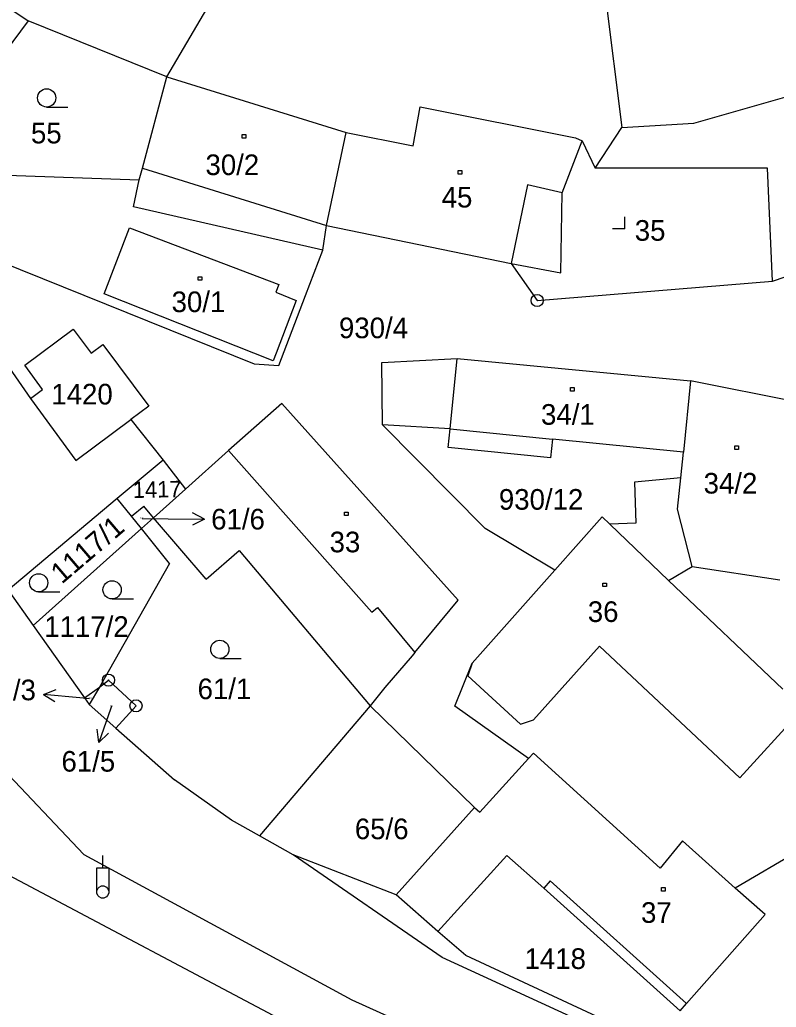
# Model space of a CAD drawing. Extents: x -796130 to -793145, y -1109506 to -1106267.
# Drawn here: x -794442.6 to -794380.3, y -1107911.5 to -1107830.1 of the extents above; entities that cross this region are included whole.
import ezdxf

# ---------------------------------------------------------------- set-up
doc = ezdxf.new("R2010")
doc.units = 0
for name, color, linetype in [('Komunikace', 7, 'Continuous'), ('Vrstva 1', 7, 'Continuous'), ('Vrstva 14', 7, 'Continuous'), ('Vrstva 15', 7, 'Continuous'), ('Vrstva 16', 7, 'Continuous'), ('Vrstva 2', 7, 'Continuous'), ('Vrstva 23', 7, 'Continuous'), ('Vrstva 25', 7, 'Continuous'), ('Vrstva 26', 7, 'Continuous'), ('Vrstva 28', 7, 'Continuous')]:
    doc.layers.add(name, color=color, linetype=linetype)

msp = doc.modelspace()

# ---------------------------------------------------------------- linework, layer by layer
at = {"layer": 'Komunikace'}
for p, q in [((-794432.56, -1107871.2), (-794430.41, -1107871.22)), ((-794436.9, -1107886.04), (-794437.7, -1107885.97)), ((-794435.07, -1107886.66), (-794435.13, -1107886.82))]:
    msp.add_line(p, q, dxfattribs=at)
at = {"layer": 'Vrstva 1'}
for p, q in [((-794395.39, -1107820.21), (-794393.06, -1107838.97)), ((-794430.51, -1107834.81), (-794422.52, -1107821.15)), ((-794453.1, -1107822.64), (-794441.95, -1107830.18)), ((-794441.95, -1107830.18), (-794444.77, -1107833.97)), ((-794430.51, -1107834.81), (-794441.95, -1107830.18)), ((-794432.52, -1107842.33), (-794430.51, -1107834.81)), ((-794430.51, -1107834.81), (-794415.75, -1107839.4)), ((-794387.13, -1107838.61), (-794372.24, -1107834.39)), ((-794410.24, -1107840.5), (-794409.66, -1107837.28)), ((-794409.66, -1107837.28), (-794396.87, -1107839.84)), ((-794393.06, -1107838.97), (-794387.13, -1107838.61)), ((-794417.38, -1107847.06), (-794415.75, -1107839.4)), ((-794415.75, -1107839.4), (-794410.24, -1107840.5)), ((-794395.24, -1107842.33), (-794393.06, -1107838.97)), ((-794397.98, -1107844.36), (-794396.32, -1107840.08)), ((-794396.87, -1107839.84), (-794396.32, -1107840.08)), ((-794396.32, -1107840.08), (-794395.24, -1107842.33)), ((-794445.24, -1107842.84), (-794432.79, -1107843.3)), ((-794432.79, -1107843.3), (-794432.52, -1107842.33)), ((-794381.05, -1107842.34), (-794395.24, -1107842.33)), ((-794380.64, -1107851.64), (-794381.05, -1107842.34)), ((-794433.26, -1107845.52), (-794432.79, -1107843.3)), ((-794398.07, -1107850.95), (-794397.98, -1107844.36)), ((-794417.69, -1107849.09), (-794433.26, -1107845.52)), ((-794417.69, -1107849.09), (-794417.38, -1107847.06)), ((-794417.38, -1107847.06), (-794402.16, -1107850.17)), ((-794451.41, -1107847.35), (-794441.76, -1107861.32)), ((-794380.64, -1107851.64), (-794371.7, -1107848.58)), ((-794419.11, -1107852.83), (-794417.69, -1107849.09)), ((-794444.34, -1107850), (-794423.33, -1107858.45)), ((-794402.16, -1107850.17), (-794398.07, -1107850.95)), ((-794402.16, -1107850.17), (-794400.02, -1107853.23)), ((-794400.02, -1107853.23), (-794380.64, -1107851.64)), ((-794421.31, -1107858.58), (-794419.11, -1107852.83)), ((-794442.22, -1107858.55), (-794438.24, -1107855.59)), ((-794438.24, -1107855.59), (-794436.75, -1107857.57)), ((-794436.75, -1107857.57), (-794435.79, -1107856.85)), ((-794435.79, -1107856.85), (-794432.01, -1107861.93)), ((-794423.33, -1107858.45), (-794421.31, -1107858.58)), ((-794412.83, -1107858.33), (-794406.62, -1107858)), ((-794412.75, -1107863.49), (-794412.83, -1107858.33)), ((-794406.62, -1107858), (-794387.41, -1107859.84)), ((-794440.76, -1107860.57), (-794442.22, -1107858.55)), ((-794387.41, -1107859.84), (-794387.99, -1107865.72)), ((-794378.6, -1107861.62), (-794387.41, -1107859.84)), ((-794441.76, -1107861.32), (-794440.76, -1107860.57)), ((-794441.76, -1107861.32), (-794438.01, -1107866.41)), ((-794432.01, -1107861.93), (-794433.5, -1107863.04)), ((-794421.05, -1107861.72), (-794425.45, -1107865.58)), ((-794406.54, -1107877.92), (-794421.05, -1107861.72)), ((-794438.01, -1107866.41), (-794433.5, -1107863.04)), ((-794433.5, -1107863.04), (-794430.83, -1107866.38)), ((-794404.3, -1107872.03), (-794412.75, -1107863.49)), ((-794407.2, -1107863.81), (-794412.75, -1107863.49)), ((-794407.35, -1107865.35), (-794407.2, -1107863.81)), ((-794398.77, -1107864.65), (-794398.92, -1107866.19)), ((-794387.99, -1107865.72), (-794398.77, -1107864.65)), ((-794428.98, -1107868.78), (-794425.45, -1107865.58)), ((-794398.92, -1107866.19), (-794407.35, -1107865.35)), ((-794388.21, -1107867.85), (-794387.99, -1107865.72)), ((-794430.83, -1107866.38), (-794434.61, -1107869.56)), ((-794430.83, -1107866.38), (-794428.98, -1107868.78)), ((-794388.21, -1107867.85), (-794392.01, -1107868.19)), ((-794392.01, -1107868.19), (-794391.91, -1107871.59)), ((-794428.98, -1107868.78), (-794431.61, -1107871.13)), ((-794434.61, -1107869.56), (-794443.59, -1107877.11)), ((-794433.44, -1107871), (-794434.61, -1107869.56)), ((-794433.44, -1107871), (-794432.43, -1107870.17)), ((-794431.61, -1107871.13), (-794432.43, -1107870.17)), ((-794432.61, -1107872.03), (-794433.44, -1107871)), ((-794431.61, -1107871.13), (-794432.61, -1107872.03)), ((-794427.29, -1107876.2), (-794431.61, -1107871.13)), ((-794394.67, -1107871.07), (-794398.56, -1107875.44)), ((-794394.04, -1107871.67), (-794394.67, -1107871.07)), ((-794432.61, -1107872.03), (-794441.54, -1107880)), ((-794430.29, -1107874.91), (-794432.61, -1107872.03)), ((-794398.56, -1107875.44), (-794404.3, -1107872.03)), ((-794391.91, -1107871.59), (-794394.04, -1107871.67)), ((-794389.2, -1107876.29), (-794394.04, -1107871.67)), ((-794427.29, -1107876.2), (-794424.58, -1107873.83)), ((-794424.58, -1107873.83), (-794413.78, -1107886.62)), ((-794430.29, -1107874.91), (-794436.08, -1107885.08)), ((-794405.39, -1107883.11), (-794398.56, -1107875.44)), ((-794389.2, -1107876.29), (-794387.27, -1107875.15)), ((-794387.27, -1107875.15), (-794380.04, -1107876.26)), ((-794379.8, -1107885.26), (-794389.2, -1107876.29)), ((-794443.59, -1107877.11), (-794441.54, -1107880)), ((-794410.09, -1107882.23), (-794406.54, -1107877.92)), ((-794441.54, -1107880), (-794437.3, -1107885.98)), ((-794410.33, -1107882.52), (-794412.56, -1107885.12)), ((-794410.09, -1107882.23), (-794410.33, -1107882.52)), ((-794406.8, -1107886.65), (-794405.39, -1107883.11)), ((-794437.3, -1107885.98), (-794436.08, -1107885.08)), ((-794436.08, -1107885.08), (-794436.91, -1107886.53)), ((-794436.08, -1107885.08), (-794435.32, -1107884.51)), ((-794435.32, -1107884.51), (-794433.06, -1107886.63)), ((-794412.56, -1107885.12), (-794413.78, -1107886.62)), ((-794437.3, -1107885.98), (-794436.91, -1107886.53)), ((-794436.91, -1107886.53), (-794434.71, -1107888.47)), ((-794433.06, -1107886.63), (-794434.71, -1107888.47)), ((-794413.78, -1107886.62), (-794422.9, -1107897.35)), ((-794413.78, -1107886.62), (-794405.18, -1107895.01)), ((-794400.75, -1107890.98), (-794406.8, -1107886.65)), ((-794434.71, -1107888.47), (-794429.88, -1107892.72)), ((-794404.76, -1107895.4), (-794400.75, -1107890.98)), ((-794400.75, -1107890.98), (-794400.33, -1107890.52)), ((-794389.89, -1107900), (-794400.33, -1107890.52)), ((-794425.2, -1107896.05), (-794429.88, -1107892.72)), ((-794405.18, -1107895.01), (-794411.63, -1107902.2)), ((-794405.18, -1107895.01), (-794404.76, -1107895.4)), ((-794422.9, -1107897.35), (-794425.2, -1107896.05)), ((-794420.12, -1107898.91), (-794422.9, -1107897.35)), ((-794447.88, -1107898.28), (-794403.89, -1107921.59)), ((-794388.06, -1107897.76), (-794389.89, -1107900)), ((-794383.71, -1107901.64), (-794388.06, -1107897.76)), ((-794377.92, -1107898.25), (-794383.71, -1107901.64)), ((-794411.63, -1107902.2), (-794420.12, -1107898.91)), ((-794408.22, -1107905.21), (-794402.53, -1107898.96)), ((-794399.48, -1107901.64), (-794402.53, -1107898.96)), ((-794408.22, -1107905.21), (-794411.63, -1107902.2)), ((-794388.26, -1107911.75), (-794399.48, -1107901.64)), ((-794381.26, -1107903.83), (-794383.71, -1107901.64)), ((-794387.73, -1107911.15), (-794381.26, -1107903.83)), ((-794405.89, -1107907.21), (-794408.22, -1107905.21)), ((-794391.58, -1107913.85), (-794405.89, -1107907.21)), ((-794388.26, -1107911.75), (-794387.73, -1107911.15))]:
    msp.add_line(p, q, dxfattribs=at)
at = {"layer": 'Vrstva 16'}
for p, q in [((-794430.41, -1107871.22), (-794427.41, -1107871.245)), ((-794427.41, -1107871.245), (-794428.414, -1107871.736)), ((-794427.41, -1107871.245), (-794428.405, -1107870.736)), ((-794440.687, -1107885.693), (-794439.645, -1107885.288)), ((-794437.7, -1107885.97), (-794440.687, -1107885.693)), ((-794440.687, -1107885.693), (-794439.737, -1107886.283)), ((-794435.13, -1107886.82), (-794436.123, -1107889.65)), ((-794436.123, -1107889.65), (-794436.264, -1107888.541)), ((-794436.123, -1107889.65), (-794435.32, -1107888.872))]:
    msp.add_line(p, q, dxfattribs=at)
at = {"layer": 'Vrstva 2'}
for p, q in [((-794432.52, -1107842.33), (-794417.38, -1107847.06)), ((-794400.81, -1107843.7), (-794402.16, -1107850.17)), ((-794397.98, -1107844.36), (-794400.81, -1107843.7)), ((-794435.68, -1107852.67), (-794433.6, -1107847.25)), ((-794433.6, -1107847.25), (-794421.31, -1107851.92)), ((-794421.31, -1107851.92), (-794421.56, -1107852.55)), ((-794421.78, -1107858.2), (-794435.68, -1107852.67)), ((-794421.56, -1107852.55), (-794419.86, -1107853.22)), ((-794419.86, -1107853.22), (-794421.53, -1107857.56)), ((-794421.53, -1107857.56), (-794421.78, -1107858.2)), ((-794407.2, -1107863.81), (-794406.62, -1107858)), ((-794407.2, -1107863.81), (-794398.77, -1107864.65)), ((-794425.45, -1107865.58), (-794413.64, -1107878.92)), ((-794388.47, -1107870.42), (-794388.21, -1107867.85)), ((-794387.27, -1107875.15), (-794388.47, -1107870.42)), ((-794413.64, -1107878.92), (-794413.18, -1107878.54)), ((-794413.18, -1107878.54), (-794410.09, -1107882.23)), ((-794400.34, -1107887.78), (-794394.89, -1107881.71)), ((-794394.89, -1107881.71), (-794383.35, -1107892.55)), ((-794405.39, -1107883.11), (-794405.73, -1107884.16)), ((-794405.73, -1107884.16), (-794401.39, -1107888.14)), ((-794383.35, -1107892.55), (-794378.14, -1107886.86)), ((-794448.11, -1107887.49), (-794437.37, -1107898.89)), ((-794401.39, -1107888.14), (-794400.34, -1107887.78)), ((-794437.37, -1107898.89), (-794415.3, -1107910.85)), ((-794407.86, -1107907.36), (-794420.12, -1107898.91)), ((-794398.95, -1107901.05), (-794399.48, -1107901.64)), ((-794387.73, -1107911.15), (-794398.95, -1107901.05)), ((-794299.63, -1107957.06), (-794407.86, -1107907.36)), ((-794415.3, -1107910.85), (-794361.74, -1107934.98))]:
    msp.add_line(p, q, dxfattribs=at)
at = {"layer": 'Vrstva 23'}
for p, q in [((-794440.42, -1107837.29), (-794438.67, -1107837.29)), ((-794392.82, -1107847.33), (-794392.82, -1107846.33)), ((-794392.82, -1107847.33), (-794393.82, -1107847.33)), ((-794441.08, -1107877.24), (-794439.33, -1107877.24)), ((-794435.03, -1107877.82), (-794433.28, -1107877.82)), ((-794426.16, -1107882.72), (-794424.41, -1107882.72))]:
    msp.add_line(p, q, dxfattribs=at)
for centre in [(-794440.42, -1107836.54), (-794441.08, -1107876.49), (-794435.03, -1107877.07), (-794426.16, -1107881.97)]:
    msp.add_circle(centre, 0.75, dxfattribs=at)
at = {"layer": 'Vrstva 25'}
for p, q in [((-794424.33, -1107839.55), (-794424.03, -1107839.55)), ((-794424.33, -1107839.85), (-794424.33, -1107839.55)), ((-794424.03, -1107839.55), (-794424.03, -1107839.85)), ((-794424.03, -1107839.85), (-794424.33, -1107839.85)), ((-794406.52, -1107842.51), (-794406.22, -1107842.51)), ((-794406.52, -1107842.81), (-794406.52, -1107842.51)), ((-794406.22, -1107842.81), (-794406.52, -1107842.81)), ((-794406.22, -1107842.51), (-794406.22, -1107842.81)), ((-794427.94, -1107851.27), (-794427.64, -1107851.27)), ((-794427.94, -1107851.57), (-794427.94, -1107851.27)), ((-794427.64, -1107851.57), (-794427.94, -1107851.57)), ((-794427.64, -1107851.27), (-794427.64, -1107851.57)), ((-794397.29, -1107860.41), (-794396.99, -1107860.41)), ((-794397.29, -1107860.71), (-794397.29, -1107860.41)), ((-794396.99, -1107860.71), (-794397.29, -1107860.71)), ((-794396.99, -1107860.41), (-794396.99, -1107860.71)), ((-794383.76, -1107865.2), (-794383.46, -1107865.2)), ((-794383.76, -1107865.5), (-794383.76, -1107865.2)), ((-794383.46, -1107865.5), (-794383.76, -1107865.5)), ((-794383.46, -1107865.2), (-794383.46, -1107865.5)), ((-794415.88, -1107870.66), (-794415.58, -1107870.66)), ((-794415.88, -1107870.96), (-794415.88, -1107870.66)), ((-794415.58, -1107870.96), (-794415.88, -1107870.96)), ((-794415.58, -1107870.66), (-794415.58, -1107870.96)), ((-794394.63, -1107876.51), (-794394.33, -1107876.51)), ((-794394.63, -1107876.81), (-794394.63, -1107876.51)), ((-794394.33, -1107876.81), (-794394.63, -1107876.81)), ((-794394.33, -1107876.51), (-794394.33, -1107876.81)), ((-794389.8, -1107901.59), (-794389.5, -1107901.59)), ((-794389.8, -1107901.89), (-794389.8, -1107901.59)), ((-794389.5, -1107901.89), (-794389.8, -1107901.89)), ((-794389.5, -1107901.59), (-794389.5, -1107901.89))]:
    msp.add_line(p, q, dxfattribs=at)
at = {"layer": 'Vrstva 26'}
for p, q in [((-794435.8, -1107899.97), (-794435.8, -1107898.97)), ((-794436.3, -1107901.97), (-794436.3, -1107899.97)), ((-794436.3, -1107899.97), (-794435.3, -1107899.97)), ((-794435.3, -1107899.97), (-794435.3, -1107901.97)), ((-794436.2, -1107901.67), (-794436.1, -1107901.57)), ((-794436.1, -1107901.57), (-794435.9, -1107901.47)), ((-794435.9, -1107901.47), (-794435.7, -1107901.47)), ((-794435.7, -1107901.47), (-794435.5, -1107901.57)), ((-794435.5, -1107901.57), (-794435.4, -1107901.67)), ((-794436.3, -1107901.87), (-794436.2, -1107901.67)), ((-794436.3, -1107902.07), (-794436.3, -1107901.87)), ((-794436.2, -1107902.27), (-794436.3, -1107902.07)), ((-794436.1, -1107902.37), (-794436.2, -1107902.27)), ((-794435.9, -1107902.47), (-794436.1, -1107902.37)), ((-794435.8, -1107901.97), (-794435.8, -1107901.97)), ((-794435.5, -1107902.37), (-794435.7, -1107902.47)), ((-794435.4, -1107902.27), (-794435.5, -1107902.37)), ((-794435.4, -1107901.67), (-794435.3, -1107901.87)), ((-794435.3, -1107902.07), (-794435.4, -1107902.27)), ((-794435.3, -1107901.87), (-794435.3, -1107902.07)), ((-794435.7, -1107902.47), (-794435.9, -1107902.47))]:
    msp.add_line(p, q, dxfattribs=at)
at = {"layer": 'Vrstva 28'}
for centre, radius in [((-794400.02, -1107853.23), 0.5), ((-794400.02, -1107853.23), 0.01), ((-794435.32, -1107884.51), 0.5), ((-794435.32, -1107884.51), 0.01), ((-794433.06, -1107886.63), 0.5), ((-794433.06, -1107886.63), 0.01)]:
    msp.add_circle(centre, radius, dxfattribs=at)

# ---------------------------------------------------------------- texts
at = {"layer": 'Vrstva 14'}
for s, height, p in [('55', 1.7, (-794441.71, -1107840.29)), ('930/4', 1.7, (-794416.35, -1107856.34)), ('1420', 1.7, (-794440.035, -1107861.8)), ('930/12', 1.7, (-794403.18, -1107870.47)), ('61/6', 0.1, (-794432.708, -1107871.2)), ('1117/2', 1.7, (-794440.616, -1107880.95)), ('61/1', 1.7, (-794427.99, -1107886.08)), ('1117/3', 0.1, (-794437.11, -1107886.04)), ('61/5', 0.1, (-794435.219, -1107886.66)), ('65/6', 1.7, (-794415.04, -1107897.62)), ('1418', 1.7, (-794401.069, -1107908.31))]:
    msp.add_text(s, height=height, dxfattribs=at).set_placement(p)
for s, height, rotation, p in [('1417', 1.35, 1.04769, (-794433.317, -1107869.506)), ('1117/1', 1.7, 40.44843, (-794439.171, -1107876.646))]:
    msp.add_text(s, height=height, rotation=rotation, dxfattribs=at).set_placement(p)
at = {"layer": 'Vrstva 15'}
for s, p in [('30/2', (-794427.34, -1107842.9)), ('45', (-794407.89, -1107845.57)), ('35', (-794391.99, -1107848.31)), ('30/1', (-794430.13, -1107854.19)), ('34/1', (-794399.71, -1107863.47)), ('34/2', (-794386.32, -1107869.14)), ('33', (-794417.12, -1107873.98)), ('36', (-794395.86, -1107879.72)), ('37', (-794391.473, -1107904.51))]:
    msp.add_text(s, height=1.7, dxfattribs=at).set_placement(p)
at = {"layer": 'Vrstva 16'}
for s, p in [('61/6', (-794426.873, -1107872.1)), ('1117/3', (-794448.256, -1107886.17)), ('61/5', (-794439.2, -1107892.05))]:
    msp.add_text(s, height=1.7, dxfattribs=at).set_placement(p)

doc.saveas('drawing.dxf')
